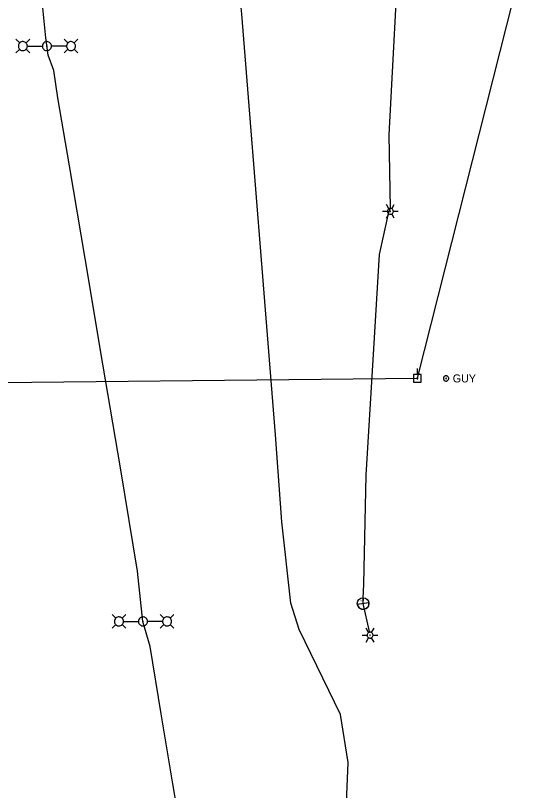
# Model space of a CAD drawing. Extents: x 600849 to 606371, y 330010 to 403088.
# Drawn here: x 604292.3 to 604540.4, y 338589.4 to 338962.3 of the extents above; entities that cross this region are included whole.
import ezdxf

# ---------------------------------------------------------------- set-up
doc = ezdxf.new("R2010")
doc.units = 0
for name, color, linetype in [('E_FTMS_Conduit', 7, 'Continuous'), ('E_LTG', 7, 'Continuous'), ('E_LTG_CID', 7, 'Continuous'), ('E_UTL_EGuyWire', 7, 'Continuous'), ('E_UTL_EPowerPole', 7, 'Continuous'), ('E_UTL_Overhead', 7, 'Continuous')]:
    doc.layers.add(name, color=color, linetype=linetype)

# ---------------------------------------------------------------- blocks, each defined once
blk = doc.blocks.new('_U273')
at = {"layer": 'E_LTG'}
blk.add_lwpolyline([(0.001, -0.171), (0.001, 0.172)], dxfattribs=at)
blk.add_circle((0.001, 0), 0.171, dxfattribs=at)
blk.add_arc((0.001, 0), 0.171, 90, 270, dxfattribs=at)
blk.add_text('L', height=0.108, dxfattribs=at).set_placement((0.066, -0.042))

msp = doc.modelspace()

# ---------------------------------------------------------------- linework, layer by layer
at = {"layer": 'E_FTMS_Conduit'}
msp.add_lwpolyline([(604450.59, 338564.2), (604452.27, 338602.89), (604448.51, 338625.98), (604428.67, 338666.96), (604424.69, 338679.58), (604420.37, 338718.72), (604417.24, 338760.59), (604401.15, 338962.95), (604399.61, 338977.58), (604396.13, 339005.93), (604382.32, 339091.9), (604379.91, 339100.81)], dxfattribs=at)
at = {"layer": 'E_LTG'}
for points in [[(604294.28, 338949.12), (604292.5, 338950.9)], [(604297.98, 338947.6), (604297.94, 338948.01), (604297.83, 338948.41), (604297.64, 338948.78), (604297.38, 338949.1), (604297.07, 338949.37), (604296.71, 338949.58), (604296.32, 338949.72), (604295.91, 338949.78), (604295.5, 338949.76), (604295.09, 338949.66), (604294.72, 338949.49), (604294.38, 338949.25), (604294.1, 338948.95), (604293.87, 338948.6), (604293.72, 338948.22), (604293.64, 338947.81), (604293.64, 338947.4), (604293.72, 338946.99), (604293.87, 338946.61), (604294.1, 338946.26), (604294.38, 338945.96), (604294.72, 338945.72), (604295.09, 338945.55), (604295.5, 338945.45), (604295.91, 338945.43), (604296.32, 338945.49), (604296.71, 338945.62), (604297.07, 338945.83), (604297.38, 338946.1), (604297.64, 338946.43), (604297.83, 338946.79), (604297.94, 338947.19), (604297.98, 338947.6)], [(604297.33, 338949.12), (604299.11, 338950.9)], [(604309.55, 338947.6), (604309.51, 338948.01), (604309.39, 338948.41), (604309.2, 338948.78), (604308.95, 338949.1), (604308.63, 338949.37), (604308.28, 338949.58), (604307.88, 338949.72), (604307.47, 338949.78), (604307.06, 338949.76), (604306.66, 338949.66), (604306.28, 338949.49), (604305.95, 338949.25), (604305.66, 338948.95), (604305.44, 338948.6), (604305.28, 338948.22), (604305.21, 338947.81), (604305.21, 338947.4), (604305.28, 338946.99), (604305.44, 338946.61), (604305.66, 338946.26), (604305.95, 338945.96), (604306.28, 338945.72), (604306.66, 338945.55), (604307.06, 338945.45), (604307.47, 338945.43), (604307.88, 338945.49), (604308.28, 338945.62), (604308.63, 338945.83), (604308.95, 338946.1), (604309.2, 338946.43), (604309.39, 338946.79), (604309.51, 338947.19), (604309.55, 338947.6)], [(604317.45, 338949.13), (604315.67, 338950.9)], [(604321.15, 338947.6), (604321.11, 338948.01), (604320.99, 338948.41), (604320.8, 338948.78), (604320.55, 338949.1), (604320.24, 338949.37), (604319.88, 338949.58), (604319.49, 338949.72), (604319.08, 338949.78), (604318.66, 338949.76), (604318.26, 338949.66), (604317.89, 338949.49), (604317.55, 338949.25), (604317.26, 338948.95), (604317.04, 338948.6), (604316.89, 338948.22), (604316.81, 338947.81), (604316.81, 338947.4), (604316.89, 338946.99), (604317.04, 338946.61), (604317.26, 338946.26), (604317.55, 338945.96), (604317.89, 338945.72), (604318.26, 338945.55), (604318.66, 338945.45), (604319.08, 338945.43), (604319.49, 338945.49), (604319.88, 338945.62), (604320.24, 338945.83), (604320.55, 338946.1), (604320.8, 338946.43), (604320.99, 338946.79), (604321.11, 338947.19), (604321.15, 338947.6)], [(604320.5, 338949.13), (604322.28, 338950.9)], [(604294.28, 338946.08), (604292.5, 338944.3)], [(604297.33, 338946.08), (604299.11, 338944.3)], [(604298.02, 338947.6), (604305.2, 338947.6)], [(604307.54, 338947.6), (604307.53, 338947.63), (604307.53, 338947.66), (604307.51, 338947.69), (604307.49, 338947.72), (604307.47, 338947.74), (604307.44, 338947.75), (604307.41, 338947.76), (604307.38, 338947.77), (604307.35, 338947.77), (604307.32, 338947.76), (604307.29, 338947.75), (604307.26, 338947.73), (604307.24, 338947.7), (604307.22, 338947.68), (604307.21, 338947.65), (604307.21, 338947.62), (604307.21, 338947.59), (604307.21, 338947.56), (604307.22, 338947.53), (604307.24, 338947.5), (604307.26, 338947.48), (604307.29, 338947.46), (604307.32, 338947.44), (604307.35, 338947.44), (604307.38, 338947.44), (604307.41, 338947.44), (604307.44, 338947.45), (604307.47, 338947.47), (604307.49, 338947.49), (604307.51, 338947.51), (604307.53, 338947.54), (604307.53, 338947.57), (604307.54, 338947.6)], [(604316.76, 338947.6), (604309.58, 338947.6)], [(604317.45, 338946.08), (604315.67, 338944.3)], [(604320.5, 338946.08), (604322.28, 338944.3)], [(604471.8, 338869.35), (604470.61, 338871.41)], [(604473.23, 338869.35), (604474.42, 338871.41)], [(604468.71, 338868.11), (604471.09, 338868.11)], [(604470.61, 338864.81), (604471.8, 338866.87)], [(604473.95, 338868.11), (604473.92, 338868.38), (604473.84, 338868.64), (604473.72, 338868.88), (604473.55, 338869.09), (604473.35, 338869.27), (604473.11, 338869.41), (604472.85, 338869.5), (604472.59, 338869.54), (604472.31, 338869.52), (604472.05, 338869.46), (604471.8, 338869.35), (604471.58, 338869.19), (604471.39, 338868.99), (604471.25, 338868.76), (604471.15, 338868.51), (604471.1, 338868.24), (604471.1, 338867.97), (604471.15, 338867.71), (604471.25, 338867.45), (604471.39, 338867.22), (604471.58, 338867.03), (604471.8, 338866.87), (604472.05, 338866.76), (604472.31, 338866.69), (604472.59, 338866.68), (604472.85, 338866.72), (604473.11, 338866.81), (604473.35, 338866.94), (604473.55, 338867.12), (604473.72, 338867.34), (604473.84, 338867.58), (604473.92, 338867.84), (604473.95, 338868.11)], [(604473.95, 338868.11), (604473.92, 338868.38), (604473.84, 338868.64), (604473.72, 338868.88), (604473.55, 338869.09), (604473.35, 338869.27), (604473.11, 338869.41), (604472.85, 338869.5), (604472.59, 338869.54), (604472.31, 338869.52), (604472.05, 338869.46), (604471.8, 338869.35), (604471.58, 338869.19), (604471.39, 338868.99), (604471.25, 338868.76), (604471.15, 338868.51), (604471.1, 338868.24), (604471.1, 338867.97), (604471.15, 338867.71), (604471.25, 338867.45), (604471.39, 338867.22), (604471.58, 338867.03), (604471.8, 338866.87), (604472.05, 338866.76), (604472.31, 338866.69), (604472.59, 338866.68), (604472.85, 338866.72), (604473.11, 338866.81), (604473.35, 338866.94), (604473.55, 338867.12), (604473.72, 338867.34), (604473.84, 338867.58), (604473.92, 338867.84), (604473.95, 338868.11)], [(604473.95, 338868.11), (604473.92, 338868.38), (604473.84, 338868.64), (604473.72, 338868.88), (604473.55, 338869.09), (604473.35, 338869.27), (604473.11, 338869.41), (604472.85, 338869.5), (604472.59, 338869.54), (604472.31, 338869.52), (604472.05, 338869.46), (604471.8, 338869.35), (604471.58, 338869.19), (604471.39, 338868.99), (604471.25, 338868.76), (604471.15, 338868.51), (604471.1, 338868.24), (604471.1, 338867.97), (604471.15, 338867.71), (604471.25, 338867.45), (604471.39, 338867.22), (604471.58, 338867.03), (604471.8, 338866.87), (604472.05, 338866.76), (604472.31, 338866.69), (604472.59, 338866.68), (604472.85, 338866.72), (604473.11, 338866.81), (604473.35, 338866.94), (604473.55, 338867.12), (604473.72, 338867.34), (604473.84, 338867.58), (604473.92, 338867.84), (604473.95, 338868.11)], [(604472.64, 338868.11), (604472.63, 338868.13), (604472.63, 338868.15), (604472.62, 338868.17), (604472.6, 338868.19), (604472.59, 338868.21), (604472.57, 338868.22), (604472.55, 338868.22), (604472.52, 338868.23), (604472.5, 338868.23), (604472.48, 338868.22), (604472.46, 338868.21), (604472.44, 338868.2), (604472.42, 338868.18), (604472.41, 338868.16), (604472.4, 338868.14), (604472.4, 338868.12), (604472.4, 338868.1), (604472.4, 338868.07), (604472.41, 338868.05), (604472.42, 338868.03), (604472.44, 338868.02), (604472.46, 338868.01), (604472.48, 338868), (604472.5, 338867.99), (604472.52, 338867.99), (604472.55, 338867.99), (604472.57, 338868), (604472.59, 338868.01), (604472.6, 338868.03), (604472.62, 338868.04), (604472.63, 338868.06), (604472.63, 338868.09), (604472.64, 338868.11)], [(604474.42, 338864.81), (604473.23, 338866.87)], [(604473.95, 338868.11), (604476.33, 338868.11)], [(604340.47, 338672.3), (604338.69, 338674.08)], [(604344.17, 338670.78), (604344.13, 338671.19), (604344.02, 338671.59), (604343.83, 338671.96), (604343.57, 338672.28), (604343.26, 338672.56), (604342.9, 338672.76), (604342.51, 338672.9), (604342.1, 338672.96), (604341.69, 338672.94), (604341.28, 338672.84), (604340.91, 338672.67), (604340.57, 338672.43), (604340.29, 338672.13), (604340.06, 338671.78), (604339.91, 338671.4), (604339.83, 338670.99), (604339.83, 338670.58), (604339.91, 338670.17), (604340.06, 338669.79), (604340.29, 338669.44), (604340.57, 338669.14), (604340.91, 338668.9), (604341.28, 338668.73), (604341.69, 338668.63), (604342.1, 338668.61), (604342.51, 338668.67), (604342.9, 338668.8), (604343.26, 338669.01), (604343.57, 338669.28), (604343.83, 338669.61), (604344.02, 338669.97), (604344.13, 338670.37), (604344.17, 338670.78)], [(604343.52, 338672.3), (604345.3, 338674.08)], [(604355.74, 338670.78), (604355.7, 338671.19), (604355.58, 338671.59), (604355.39, 338671.96), (604355.14, 338672.28), (604354.82, 338672.55), (604354.47, 338672.76), (604354.07, 338672.9), (604353.66, 338672.96), (604353.25, 338672.94), (604352.85, 338672.84), (604352.47, 338672.67), (604352.14, 338672.43), (604351.85, 338672.13), (604351.63, 338671.78), (604351.47, 338671.4), (604351.4, 338670.99), (604351.4, 338670.58), (604351.47, 338670.17), (604351.63, 338669.79), (604351.85, 338669.44), (604352.14, 338669.14), (604352.47, 338668.9), (604352.85, 338668.73), (604353.25, 338668.63), (604353.66, 338668.61), (604354.07, 338668.67), (604354.47, 338668.8), (604354.82, 338669.01), (604355.14, 338669.28), (604355.39, 338669.61), (604355.58, 338669.97), (604355.7, 338670.37), (604355.74, 338670.78)], [(604363.64, 338672.31), (604361.86, 338674.08)], [(604367.34, 338670.78), (604367.3, 338671.19), (604367.18, 338671.59), (604366.99, 338671.96), (604366.74, 338672.28), (604366.43, 338672.55), (604366.07, 338672.76), (604365.68, 338672.9), (604365.27, 338672.96), (604364.85, 338672.94), (604364.45, 338672.84), (604364.08, 338672.67), (604363.74, 338672.43), (604363.45, 338672.13), (604363.23, 338671.78), (604363.08, 338671.4), (604363, 338670.99), (604363, 338670.58), (604363.08, 338670.17), (604363.23, 338669.79), (604363.45, 338669.44), (604363.74, 338669.14), (604364.08, 338668.9), (604364.45, 338668.73), (604364.85, 338668.63), (604365.27, 338668.61), (604365.68, 338668.67), (604366.07, 338668.8), (604366.43, 338669.01), (604366.74, 338669.28), (604366.99, 338669.61), (604367.18, 338669.97), (604367.3, 338670.37), (604367.34, 338670.78)], [(604366.69, 338672.31), (604368.47, 338674.08)], [(604340.47, 338669.26), (604338.69, 338667.48)], [(604343.52, 338669.26), (604345.3, 338667.48)], [(604344.21, 338670.78), (604351.39, 338670.78)], [(604353.73, 338670.78), (604353.72, 338670.81), (604353.72, 338670.84), (604353.7, 338670.87), (604353.68, 338670.9), (604353.66, 338670.92), (604353.63, 338670.93), (604353.6, 338670.94), (604353.57, 338670.95), (604353.54, 338670.95), (604353.51, 338670.94), (604353.48, 338670.93), (604353.45, 338670.91), (604353.43, 338670.89), (604353.41, 338670.86), (604353.4, 338670.83), (604353.4, 338670.8), (604353.4, 338670.77), (604353.4, 338670.74), (604353.41, 338670.71), (604353.43, 338670.68), (604353.45, 338670.66), (604353.48, 338670.64), (604353.51, 338670.63), (604353.54, 338670.62), (604353.57, 338670.62), (604353.6, 338670.62), (604353.63, 338670.63), (604353.66, 338670.65), (604353.68, 338670.67), (604353.7, 338670.69), (604353.72, 338670.72), (604353.72, 338670.75), (604353.73, 338670.78)], [(604362.95, 338670.78), (604355.77, 338670.78)], [(604363.64, 338669.26), (604361.86, 338667.48)], [(604366.69, 338669.26), (604368.47, 338667.48)], [(604462.03, 338665.4), (604460.84, 338667.46)], [(604464.17, 338664.16), (604464.14, 338664.43), (604464.07, 338664.69), (604463.94, 338664.93), (604463.78, 338665.14), (604463.57, 338665.32), (604463.33, 338665.46), (604463.08, 338665.55), (604462.81, 338665.59), (604462.54, 338665.57), (604462.27, 338665.51), (604462.03, 338665.4), (604461.81, 338665.24), (604461.62, 338665.04), (604461.47, 338664.81), (604461.37, 338664.56), (604461.32, 338664.29), (604461.32, 338664.02), (604461.37, 338663.76), (604461.47, 338663.5), (604461.62, 338663.27), (604461.81, 338663.08), (604462.03, 338662.92), (604462.27, 338662.81), (604462.54, 338662.74), (604462.81, 338662.73), (604463.08, 338662.77), (604463.33, 338662.86), (604463.57, 338662.99), (604463.78, 338663.17), (604463.94, 338663.39), (604464.07, 338663.63), (604464.14, 338663.89), (604464.17, 338664.16)], [(604464.17, 338664.16), (604464.14, 338664.43), (604464.07, 338664.69), (604463.94, 338664.93), (604463.78, 338665.14), (604463.57, 338665.32), (604463.33, 338665.46), (604463.08, 338665.55), (604462.81, 338665.59), (604462.54, 338665.57), (604462.27, 338665.51), (604462.03, 338665.4), (604461.81, 338665.24), (604461.62, 338665.04), (604461.47, 338664.81), (604461.37, 338664.56), (604461.32, 338664.29), (604461.32, 338664.02), (604461.37, 338663.76), (604461.47, 338663.5), (604461.62, 338663.27), (604461.81, 338663.08), (604462.03, 338662.92), (604462.27, 338662.81), (604462.54, 338662.74), (604462.81, 338662.73), (604463.08, 338662.77), (604463.33, 338662.86), (604463.57, 338662.99), (604463.78, 338663.17), (604463.94, 338663.39), (604464.07, 338663.63), (604464.14, 338663.89), (604464.17, 338664.16)], [(604464.17, 338664.16), (604464.14, 338664.43), (604464.07, 338664.69), (604463.94, 338664.93), (604463.78, 338665.14), (604463.57, 338665.32), (604463.33, 338665.46), (604463.08, 338665.55), (604462.81, 338665.59), (604462.54, 338665.57), (604462.27, 338665.51), (604462.03, 338665.4), (604461.81, 338665.24), (604461.62, 338665.04), (604461.47, 338664.81), (604461.37, 338664.56), (604461.32, 338664.29), (604461.32, 338664.02), (604461.37, 338663.76), (604461.47, 338663.5), (604461.62, 338663.27), (604461.81, 338663.08), (604462.03, 338662.92), (604462.27, 338662.81), (604462.54, 338662.74), (604462.81, 338662.73), (604463.08, 338662.77), (604463.33, 338662.86), (604463.57, 338662.99), (604463.78, 338663.17), (604463.94, 338663.39), (604464.07, 338663.63), (604464.14, 338663.89), (604464.17, 338664.16)], [(604463.46, 338665.4), (604464.65, 338667.46)], [(604458.93, 338664.16), (604461.31, 338664.16)], [(604460.84, 338660.86), (604462.03, 338662.92)], [(604462.86, 338664.16), (604462.86, 338664.18), (604462.85, 338664.2), (604462.84, 338664.22), (604462.83, 338664.24), (604462.81, 338664.25), (604462.79, 338664.27), (604462.77, 338664.27), (604462.75, 338664.28), (604462.72, 338664.28), (604462.7, 338664.27), (604462.68, 338664.26), (604462.66, 338664.25), (604462.65, 338664.23), (604462.64, 338664.21), (604462.63, 338664.19), (604462.62, 338664.17), (604462.62, 338664.15), (604462.63, 338664.12), (604462.64, 338664.1), (604462.65, 338664.08), (604462.66, 338664.07), (604462.68, 338664.05), (604462.7, 338664.05), (604462.72, 338664.04), (604462.75, 338664.04), (604462.77, 338664.04), (604462.79, 338664.05), (604462.81, 338664.06), (604462.83, 338664.08), (604462.84, 338664.09), (604462.85, 338664.11), (604462.86, 338664.14), (604462.86, 338664.16)], [(604464.65, 338660.86), (604463.46, 338662.92)], [(604464.17, 338664.16), (604466.55, 338664.16)]]:
    msp.add_lwpolyline(points, dxfattribs=at)
at = {"layer": 'E_LTG_CID'}
for points in [[(604462.53, 338665.89), (604459.42, 338679.36), (604459.39, 338681.9), (604459.7, 338688.71), (604460.81, 338741.12), (604464.5, 338801.96), (604467.28, 338847.26), (604471.84, 338867.78), (604472.52, 338869.57), (604471.92, 338904.85), (604477.27, 339004.79), (604479.36, 339028.67), (604475.85, 339040.45), (604483.83, 339111.42), (604496.92, 339188.17), (604513.35, 339300.5)], [(604353.57, 338670.76), (604353.57, 338670.76), (604350.99, 338694.94), (604342.69, 338744.69), (604334.31, 338794.61), (604325.73, 338845.48), (604318.29, 338889.92), (604312.59, 338922.72), (604310.7, 338935.86), (604307.95, 338943.2), (604306.89, 338951.53), (604305.14, 338969.31)], [(604378.81, 338528.04), (604367.93, 338592.68), (604362.35, 338626.27), (604357.03, 338658.73), (604353.57, 338670.76)]]:
    msp.add_lwpolyline(points, dxfattribs=at)
at = {"layer": 'E_UTL_EGuyWire'}
for points in [[(604500.59, 338787.71), (604500.56, 338787.95), (604500.49, 338788.18), (604500.38, 338788.4), (604500.23, 338788.59), (604500.05, 338788.75), (604499.84, 338788.87), (604499.61, 338788.95), (604499.36, 338788.99), (604499.12, 338788.98), (604498.88, 338788.92), (604498.66, 338788.82), (604498.46, 338788.68), (604498.29, 338788.5), (604498.16, 338788.29), (604498.07, 338788.07), (604498.03, 338787.83), (604498.03, 338787.58), (604498.07, 338787.34), (604498.16, 338787.12), (604498.29, 338786.91), (604498.46, 338786.74), (604498.66, 338786.6), (604498.88, 338786.49), (604499.12, 338786.44), (604499.36, 338786.42), (604499.61, 338786.46), (604499.84, 338786.54), (604500.05, 338786.66), (604500.23, 338786.82), (604500.38, 338787.01), (604500.49, 338787.23), (604500.56, 338787.46), (604500.59, 338787.71)], [(604499.46, 338787.71), (604499.46, 338787.74), (604499.45, 338787.77), (604499.44, 338787.79), (604499.42, 338787.82), (604499.4, 338787.84), (604499.37, 338787.85), (604499.34, 338787.86), (604499.31, 338787.87), (604499.28, 338787.87), (604499.25, 338787.86), (604499.22, 338787.85), (604499.2, 338787.83), (604499.18, 338787.81), (604499.16, 338787.78), (604499.15, 338787.75), (604499.14, 338787.72), (604499.14, 338787.69), (604499.15, 338787.66), (604499.16, 338787.63), (604499.18, 338787.61), (604499.2, 338787.59), (604499.22, 338787.57), (604499.25, 338787.55), (604499.28, 338787.55), (604499.31, 338787.55), (604499.34, 338787.55), (604499.37, 338787.56), (604499.4, 338787.58), (604499.42, 338787.6), (604499.44, 338787.62), (604499.45, 338787.65), (604499.46, 338787.68), (604499.46, 338787.71)]]:
    msp.add_lwpolyline(points, dxfattribs=at)
at = {"layer": 'E_UTL_EPowerPole'}
for points in [[(604485.5, 338789.61), (604485.5, 338792.52)], [(604487.34, 338789.61), (604483.65, 338789.61)], [(604483.65, 338789.61), (604483.65, 338785.92)], [(604485.77, 338787.77), (604485.76, 338787.82), (604485.75, 338787.86), (604485.73, 338787.9), (604485.7, 338787.94), (604485.67, 338787.97), (604485.63, 338787.99), (604485.59, 338788), (604485.54, 338788.01), (604485.5, 338788.01), (604485.45, 338788), (604485.41, 338787.98), (604485.37, 338787.95), (604485.34, 338787.92), (604485.32, 338787.88), (604485.3, 338787.84), (604485.29, 338787.79), (604485.29, 338787.75), (604485.3, 338787.7), (604485.32, 338787.66), (604485.34, 338787.62), (604485.37, 338787.59), (604485.41, 338787.57), (604485.45, 338787.55), (604485.5, 338787.54), (604485.54, 338787.53), (604485.59, 338787.54), (604485.63, 338787.55), (604485.67, 338787.58), (604485.7, 338787.61), (604485.73, 338787.64), (604485.75, 338787.68), (604485.76, 338787.73), (604485.77, 338787.77)], [(604487.34, 338785.92), (604487.34, 338789.61)], [(604483.65, 338785.92), (604487.34, 338785.92)]]:
    msp.add_lwpolyline(points, dxfattribs=at)
at = {"layer": 'E_UTL_Overhead'}
msp.add_line((604485.53, 338787.77), (604542.03, 339011.12), dxfattribs=at)
msp.add_lwpolyline([(604238.08, 338785.21), (604485.53, 338787.77)], dxfattribs=at)

# ---------------------------------------------------------------- block references
at = {"layer": 'E_LTG_CID', "xscale": 16.404166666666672, "yscale": 16.404166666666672, "rotation": 97.82095686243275}
msp.add_blockref('_U273', (604459.42, 338679.36), dxfattribs=at)

# ---------------------------------------------------------------- texts
at = {"layer": 'E_UTL_EGuyWire'}
msp.add_text('GUY', height=3.85, dxfattribs=at).set_placement((604502.51, 338785.78))

doc.saveas('drawing.dxf')
